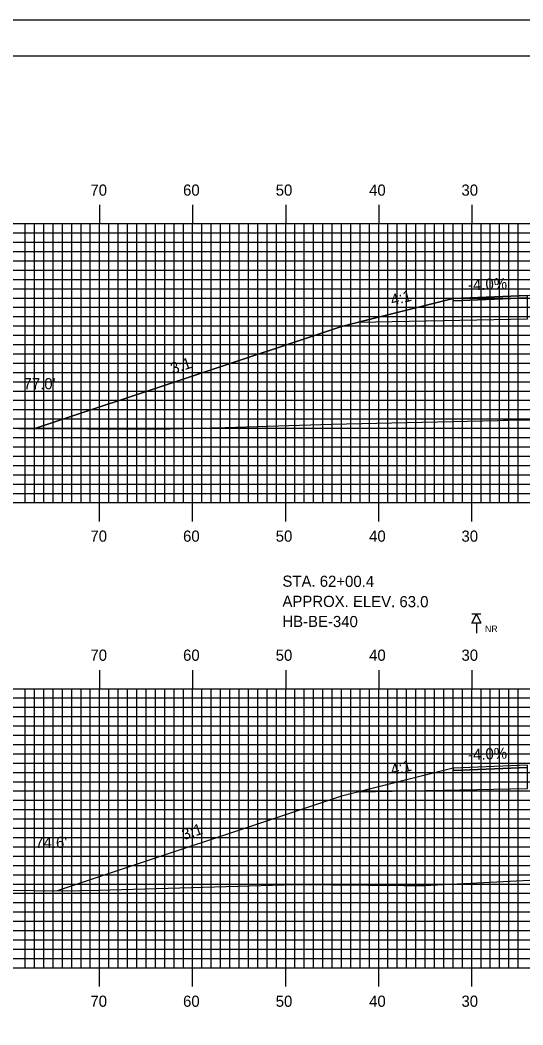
# Model space of a CAD drawing. Extents: x 1757856 to 1758199, y 442591 to 442811.
# Drawn here: x 1757943.1 to 1757997.1, y 442702.5 to 442810.5 of the extents above; entities that cross this region are included whole.
import ezdxf

# ---------------------------------------------------------------- set-up
doc = ezdxf.new("R2010")
doc.units = 0
for name, color, linetype in [('ANNOTATION', 7, 'Continuous'), ('BORDER', 7, 'Continuous'), ('BORING - NO REFUSAL', 7, 'Continuous'), ('D_Roadway_Centerline', 7, 'Continuous'), ('D_Roadway_Edge_Shoulder', 7, 'Continuous'), ('D_Roadway_SlopeLines', 7, 'Continuous'), ('D_Roadway_SubGrade', 7, 'Continuous'), ('D_Text_Standard', 7, 'Continuous'), ('H_V ANNOTATION', 7, 'Continuous'), ('MAJOR', 7, 'Continuous'), ('MINOR', 7, 'Continuous'), ('PLOT BOUNDARY', 7, 'Continuous'), ('S_Roadway_Centerline', 7, 'Continuous')]:
    doc.layers.add(name, color=color, linetype=linetype)

msp = doc.modelspace()

# ---------------------------------------------------------------- linework, layer by layer
at = {"layer": 'BORDER'}
msp.add_lwpolyline([(1757872.02, 442596.67), (1758192.02, 442596.67), (1758192.02, 442806.67), (1757872.02, 442806.67)], close=True, dxfattribs=at)
at = {"layer": 'BORING - NO REFUSAL'}
for p, q in [((1757992.6, 442746.67), (1757991.64, 442746.67)), ((1757992.12, 442745.71), (1757992.12, 442744.65))]:
    msp.add_line(p, q, dxfattribs=at)
msp.add_lwpolyline([(1757992.12, 442746.67), (1757992.6, 442745.71), (1757991.64, 442745.71)], close=True, dxfattribs=at)
at = {"layer": 'D_Roadway_Centerline'}
msp.add_lwpolyline([(1757944.65, 442766.63), (1757977.62, 442777.62), (1757979.45, 442778.07), (1757989.62, 442780.62), (1757997.62, 442780.94), (1758009.62, 442781.18), (1758021.62, 442781.42), (1758033.62, 442781.18), (1758041.62, 442780.86), (1758051.81, 442778.31), (1758060.48, 442780.48)], dxfattribs=at)
at = {"layer": 'D_Roadway_Edge_Shoulder'}
for points in [[(1757997.62, 442780.94), (1757989.62, 442780.62), (1757989.62, 442780.37), (1757997.62, 442780.69)], [(1757997.62, 442730.44), (1757989.62, 442730.12), (1757989.62, 442729.87), (1757997.62, 442730.19)]]:
    msp.add_lwpolyline(points, close=True, dxfattribs=at)
at = {"layer": 'D_Roadway_SlopeLines'}
for points in [[(1757989.62, 442780.62), (1757977.62, 442777.62), (1757944.65, 442766.63)], [(1757989.62, 442730.12), (1757977.62, 442727.12), (1757947.05, 442716.93)]]:
    msp.add_lwpolyline(points, dxfattribs=at)
at = {"layer": 'D_Roadway_SubGrade'}
for points in [[(1757997.62, 442780.27), (1757997.62, 442780.69), (1757989.62, 442780.37), (1757989.62, 442780.62), (1757979.45, 442778.07), (1757997.62, 442778.44)], [(1757997.62, 442729.77), (1757997.62, 442730.19), (1757989.62, 442729.87), (1757989.62, 442730.12), (1757979.45, 442727.57), (1757997.62, 442727.94)]]:
    msp.add_lwpolyline(points, close=True, dxfattribs=at)
at = {"layer": 'MAJOR'}
for p, q in [((1757951.62, 442790.67), (1757951.62, 442788.67)), ((1757961.62, 442790.67), (1757961.62, 442788.67)), ((1757971.62, 442790.67), (1757971.62, 442788.67)), ((1757981.62, 442790.67), (1757981.62, 442788.67)), ((1757991.62, 442790.67), (1757991.62, 442788.67)), ((1757881.62, 442788.67), (1758161.62, 442788.67)), ((1757881.62, 442788.67), (1758161.62, 442788.67)), ((1757951.62, 442758.67), (1757951.62, 442788.67)), ((1757961.62, 442758.67), (1757961.62, 442788.67)), ((1757971.62, 442758.67), (1757971.62, 442788.67)), ((1757981.62, 442758.67), (1757981.62, 442788.67)), ((1757991.62, 442758.67), (1757991.62, 442788.67)), ((1757881.62, 442783.67), (1758161.62, 442783.67)), ((1757881.62, 442778.67), (1758161.62, 442778.67)), ((1757881.62, 442773.67), (1758161.62, 442773.67)), ((1757881.62, 442768.67), (1758161.62, 442768.67)), ((1757881.62, 442763.67), (1758161.62, 442763.67)), ((1757881.62, 442758.67), (1758161.62, 442758.67)), ((1757881.62, 442758.67), (1758161.62, 442758.67)), ((1757951.62, 442756.66), (1757951.62, 442758.67)), ((1757961.62, 442756.66), (1757961.62, 442758.67)), ((1757971.62, 442756.66), (1757971.62, 442758.67)), ((1757981.62, 442756.66), (1757981.62, 442758.67)), ((1757991.62, 442756.66), (1757991.62, 442758.67)), ((1757951.62, 442740.67), (1757951.62, 442738.67)), ((1757961.62, 442740.67), (1757961.62, 442738.67)), ((1757971.62, 442740.67), (1757971.62, 442738.67)), ((1757981.62, 442740.67), (1757981.62, 442738.67)), ((1757991.62, 442740.67), (1757991.62, 442738.67)), ((1757881.62, 442738.67), (1758161.62, 442738.67)), ((1757881.62, 442738.67), (1758161.62, 442738.67)), ((1757951.62, 442708.67), (1757951.62, 442738.67)), ((1757961.62, 442708.67), (1757961.62, 442738.67)), ((1757971.62, 442708.67), (1757971.62, 442738.67)), ((1757981.62, 442708.67), (1757981.62, 442738.67)), ((1757991.62, 442708.67), (1757991.62, 442738.67)), ((1757881.62, 442733.67), (1758161.62, 442733.67)), ((1757881.62, 442728.67), (1758161.62, 442728.67)), ((1757881.62, 442723.67), (1758161.62, 442723.67)), ((1757881.62, 442718.67), (1758161.62, 442718.67)), ((1757881.62, 442713.67), (1758161.62, 442713.67)), ((1757881.62, 442708.67), (1758161.62, 442708.67)), ((1757881.62, 442708.67), (1758161.62, 442708.67)), ((1757951.62, 442706.66), (1757951.62, 442708.67)), ((1757961.62, 442706.66), (1757961.62, 442708.67)), ((1757971.62, 442706.66), (1757971.62, 442708.67)), ((1757981.62, 442706.66), (1757981.62, 442708.67)), ((1757991.62, 442706.66), (1757991.62, 442708.67))]:
    msp.add_line(p, q, dxfattribs=at)
at = {"layer": 'MINOR'}
for p, q in [((1757943.62, 442758.67), (1757943.62, 442788.67)), ((1757944.62, 442758.67), (1757944.62, 442788.67)), ((1757945.62, 442758.67), (1757945.62, 442788.67)), ((1757946.62, 442758.67), (1757946.62, 442788.67)), ((1757947.62, 442758.67), (1757947.62, 442788.67)), ((1757948.62, 442758.67), (1757948.62, 442788.67)), ((1757949.62, 442758.67), (1757949.62, 442788.67)), ((1757950.62, 442758.67), (1757950.62, 442788.67)), ((1757952.62, 442758.67), (1757952.62, 442788.67)), ((1757953.62, 442758.67), (1757953.62, 442788.67)), ((1757954.62, 442758.67), (1757954.62, 442788.67)), ((1757955.62, 442758.67), (1757955.62, 442788.67)), ((1757956.62, 442758.67), (1757956.62, 442788.67)), ((1757957.62, 442758.67), (1757957.62, 442788.67)), ((1757958.62, 442758.67), (1757958.62, 442788.67)), ((1757959.62, 442758.67), (1757959.62, 442788.67)), ((1757960.62, 442758.67), (1757960.62, 442788.67)), ((1757962.62, 442758.67), (1757962.62, 442788.67)), ((1757963.62, 442758.67), (1757963.62, 442788.67)), ((1757964.62, 442758.67), (1757964.62, 442788.67)), ((1757965.62, 442758.67), (1757965.62, 442788.67)), ((1757966.62, 442758.67), (1757966.62, 442788.67)), ((1757967.62, 442758.67), (1757967.62, 442788.67)), ((1757968.62, 442758.67), (1757968.62, 442788.67)), ((1757969.62, 442758.67), (1757969.62, 442788.67)), ((1757970.62, 442758.67), (1757970.62, 442788.67)), ((1757972.62, 442758.67), (1757972.62, 442788.67)), ((1757973.62, 442758.67), (1757973.62, 442788.67)), ((1757974.62, 442758.67), (1757974.62, 442788.67)), ((1757975.62, 442758.67), (1757975.62, 442788.67)), ((1757976.62, 442758.67), (1757976.62, 442788.67)), ((1757977.62, 442758.67), (1757977.62, 442788.67)), ((1757978.62, 442758.67), (1757978.62, 442788.67)), ((1757979.62, 442758.67), (1757979.62, 442788.67)), ((1757980.62, 442758.67), (1757980.62, 442788.67)), ((1757982.62, 442758.67), (1757982.62, 442788.67)), ((1757983.62, 442758.67), (1757983.62, 442788.67)), ((1757984.62, 442758.67), (1757984.62, 442788.67)), ((1757985.62, 442758.67), (1757985.62, 442788.67)), ((1757986.62, 442758.67), (1757986.62, 442788.67)), ((1757987.62, 442758.67), (1757987.62, 442788.67)), ((1757988.62, 442758.67), (1757988.62, 442788.67)), ((1757989.62, 442758.67), (1757989.62, 442788.67)), ((1757990.62, 442758.67), (1757990.62, 442788.67)), ((1757992.62, 442758.67), (1757992.62, 442788.67)), ((1757993.62, 442758.67), (1757993.62, 442788.67)), ((1757994.62, 442758.67), (1757994.62, 442788.67)), ((1757995.62, 442758.67), (1757995.62, 442788.67)), ((1757996.62, 442758.67), (1757996.62, 442788.67)), ((1757881.62, 442787.67), (1758161.62, 442787.67)), ((1757881.62, 442786.67), (1758161.62, 442786.67)), ((1757881.62, 442785.67), (1758161.62, 442785.67)), ((1757881.62, 442784.67), (1758161.62, 442784.67)), ((1757881.62, 442782.67), (1758161.62, 442782.67)), ((1757881.62, 442781.67), (1758161.62, 442781.67)), ((1757881.62, 442780.67), (1758161.62, 442780.67)), ((1757881.62, 442779.67), (1758161.62, 442779.67)), ((1757881.62, 442777.67), (1758161.62, 442777.67)), ((1757881.62, 442776.67), (1758161.62, 442776.67)), ((1757881.62, 442775.67), (1758161.62, 442775.67)), ((1757881.62, 442774.67), (1758161.62, 442774.67)), ((1757881.62, 442772.67), (1758161.62, 442772.67)), ((1757881.62, 442771.67), (1758161.62, 442771.67)), ((1757881.62, 442770.67), (1758161.62, 442770.67)), ((1757881.62, 442769.67), (1758161.62, 442769.67)), ((1757881.62, 442767.67), (1758161.62, 442767.67)), ((1757881.62, 442766.67), (1758161.62, 442766.67)), ((1757881.62, 442765.67), (1758161.62, 442765.67)), ((1757881.62, 442764.67), (1758161.62, 442764.67)), ((1757881.62, 442762.67), (1758161.62, 442762.67)), ((1757881.62, 442761.67), (1758161.62, 442761.67)), ((1757881.62, 442760.67), (1758161.62, 442760.67)), ((1757881.62, 442759.67), (1758161.62, 442759.67)), ((1757943.62, 442708.67), (1757943.62, 442738.67)), ((1757944.62, 442708.67), (1757944.62, 442738.67)), ((1757945.62, 442708.67), (1757945.62, 442738.67)), ((1757946.62, 442708.67), (1757946.62, 442738.67)), ((1757947.62, 442708.67), (1757947.62, 442738.67)), ((1757948.62, 442708.67), (1757948.62, 442738.67)), ((1757949.62, 442708.67), (1757949.62, 442738.67)), ((1757950.62, 442708.67), (1757950.62, 442738.67)), ((1757952.62, 442708.67), (1757952.62, 442738.67)), ((1757953.62, 442708.67), (1757953.62, 442738.67)), ((1757954.62, 442708.67), (1757954.62, 442738.67)), ((1757955.62, 442708.67), (1757955.62, 442738.67)), ((1757956.62, 442708.67), (1757956.62, 442738.67)), ((1757957.62, 442708.67), (1757957.62, 442738.67)), ((1757958.62, 442708.67), (1757958.62, 442738.67)), ((1757959.62, 442708.67), (1757959.62, 442738.67)), ((1757960.62, 442708.67), (1757960.62, 442738.67)), ((1757962.62, 442708.67), (1757962.62, 442738.67)), ((1757963.62, 442708.67), (1757963.62, 442738.67)), ((1757964.62, 442708.67), (1757964.62, 442738.67)), ((1757965.62, 442708.67), (1757965.62, 442738.67)), ((1757966.62, 442708.67), (1757966.62, 442738.67)), ((1757967.62, 442708.67), (1757967.62, 442738.67)), ((1757968.62, 442708.67), (1757968.62, 442738.67)), ((1757969.62, 442708.67), (1757969.62, 442738.67)), ((1757970.62, 442708.67), (1757970.62, 442738.67)), ((1757972.62, 442708.67), (1757972.62, 442738.67)), ((1757973.62, 442708.67), (1757973.62, 442738.67)), ((1757974.62, 442708.67), (1757974.62, 442738.67)), ((1757975.62, 442708.67), (1757975.62, 442738.67)), ((1757976.62, 442708.67), (1757976.62, 442738.67)), ((1757977.62, 442708.67), (1757977.62, 442738.67)), ((1757978.62, 442708.67), (1757978.62, 442738.67)), ((1757979.62, 442708.67), (1757979.62, 442738.67)), ((1757980.62, 442708.67), (1757980.62, 442738.67)), ((1757982.62, 442708.67), (1757982.62, 442738.67)), ((1757983.62, 442708.67), (1757983.62, 442738.67)), ((1757984.62, 442708.67), (1757984.62, 442738.67)), ((1757985.62, 442708.67), (1757985.62, 442738.67)), ((1757986.62, 442708.67), (1757986.62, 442738.67)), ((1757987.62, 442708.67), (1757987.62, 442738.67)), ((1757988.62, 442708.67), (1757988.62, 442738.67)), ((1757989.62, 442708.67), (1757989.62, 442738.67)), ((1757990.62, 442708.67), (1757990.62, 442738.67)), ((1757992.62, 442708.67), (1757992.62, 442738.67)), ((1757993.62, 442708.67), (1757993.62, 442738.67)), ((1757994.62, 442708.67), (1757994.62, 442738.67)), ((1757995.62, 442708.67), (1757995.62, 442738.67)), ((1757996.62, 442708.67), (1757996.62, 442738.67)), ((1757881.62, 442737.67), (1758161.62, 442737.67)), ((1757881.62, 442736.67), (1758161.62, 442736.67)), ((1757881.62, 442735.67), (1758161.62, 442735.67)), ((1757881.62, 442734.67), (1758161.62, 442734.67)), ((1757881.62, 442732.67), (1758161.62, 442732.67)), ((1757881.62, 442731.67), (1758161.62, 442731.67)), ((1757881.62, 442730.67), (1758161.62, 442730.67)), ((1757881.62, 442729.67), (1758161.62, 442729.67)), ((1757881.62, 442727.67), (1758161.62, 442727.67)), ((1757881.62, 442726.67), (1758161.62, 442726.67)), ((1757881.62, 442725.67), (1758161.62, 442725.67)), ((1757881.62, 442724.67), (1758161.62, 442724.67)), ((1757881.62, 442722.67), (1758161.62, 442722.67)), ((1757881.62, 442721.67), (1758161.62, 442721.67)), ((1757881.62, 442720.67), (1758161.62, 442720.67)), ((1757881.62, 442719.67), (1758161.62, 442719.67)), ((1757881.62, 442717.67), (1758161.62, 442717.67)), ((1757881.62, 442716.67), (1758161.62, 442716.67)), ((1757881.62, 442715.67), (1758161.62, 442715.67)), ((1757881.62, 442714.67), (1758161.62, 442714.67)), ((1757881.62, 442712.67), (1758161.62, 442712.67)), ((1757881.62, 442711.67), (1758161.62, 442711.67)), ((1757881.62, 442710.67), (1758161.62, 442710.67)), ((1757881.62, 442709.67), (1758161.62, 442709.67))]:
    msp.add_line(p, q, dxfattribs=at)
at = {"layer": 'PLOT BOUNDARY'}
msp.add_lwpolyline([(1757855.84, 442590.55), (1758195.84, 442590.55), (1758195.84, 442810.55), (1757855.84, 442810.55)], close=True, dxfattribs=at)
at = {"layer": 'S_Roadway_Centerline'}
for points in [[(1757942.94, 442766.64), (1757957.7, 442766.56), (1757965.12, 442766.76), (1757976.56, 442767.11), (1757994.44, 442767.5), (1757995.02, 442767.52), (1757995.51, 442767.52), (1758007.66, 442767.6), (1758013.74, 442767.97), (1758029.7, 442767.75), (1758033.59, 442767.78), (1758041.83, 442767.95), (1758055.74, 442768.41), (1758059.36, 442768.58), (1758072.67, 442768.91), (1758091.05, 442768.72)], [(1757938.97, 442717.05), (1757947.5, 442716.92), (1757951.51, 442717), (1757965.23, 442717.4), (1757972.73, 442717.6), (1757984.33, 442717.52), (1757986.5, 442717.52), (1757999.99, 442718.19), (1758004.22, 442718.16), (1758017.53, 442717.91), (1758020.15, 442717.83), (1758021.64, 442717.88), (1758029.2, 442717.87), (1758041.85, 442718.04), (1758047.73, 442718.09), (1758056.34, 442718.22), (1758061.68, 442718.34), (1758077.96, 442718.66), (1758080.02, 442718.69), (1758080.79, 442718.7), (1758100.24, 442718.9)]]:
    msp.add_lwpolyline(points, dxfattribs=at)

# ---------------------------------------------------------------- texts
at = {"layer": 'ANNOTATION'}
for s, rotation, p in [('-4.0%', 2.2906, (1757991.25, 442781.48)), ('4:1', 14.0362, (1757983.07, 442779.84)), ('3:1', 18.4348, (1757959.48, 442772.48)), ('-4.0%', 2.2906, (1757991.25, 442730.98)), ('4:1', 14.0362, (1757983.07, 442729.34)), ('3:1', 18.4348, (1757960.68, 442722.38))]:
    msp.add_text(s, height=1.2, rotation=rotation, dxfattribs=at).set_placement(p)
at = {"layer": 'BORING - NO REFUSAL'}
for s, p in [('STA. 62+00.4', (1757971.27, 442749.63)), ('APPROX. ELEV. 63.0', (1757971.27, 442747.47)), ('HB-BE-340', (1757971.26, 442745.31))]:
    msp.add_text(s, height=1.2, rotation=359.8142, dxfattribs=at).set_placement(p)
msp.add_text('NR', height=0.7, dxfattribs=at).set_placement((1757993.05, 442744.75))
at = {"layer": 'D_Text_Standard'}
for s, p in [("77.0'", (1757943.44, 442770.86)), ("74.6'", (1757944.7, 442721.54))]:
    msp.add_text(s, height=1.2, dxfattribs=at).set_placement(p)
at = {"layer": 'H_V ANNOTATION'}
for s, p in [('70', (1757950.63, 442791.67)), ('60', (1757960.59, 442791.67)), ('50', (1757970.55, 442791.67)), ('40', (1757980.59, 442791.67)), ('30', (1757990.52, 442791.67)), ('70', (1757950.63, 442754.47)), ('60', (1757960.59, 442754.47)), ('50', (1757970.55, 442754.47)), ('40', (1757980.59, 442754.47)), ('30', (1757990.52, 442754.47)), ('70', (1757950.63, 442741.67)), ('60', (1757960.59, 442741.67)), ('50', (1757970.55, 442741.67)), ('40', (1757980.59, 442741.67)), ('30', (1757990.52, 442741.67)), ('70', (1757950.63, 442704.47)), ('60', (1757960.59, 442704.47)), ('50', (1757970.55, 442704.47)), ('40', (1757980.59, 442704.47)), ('30', (1757990.52, 442704.47))]:
    msp.add_text(s, height=1.2, dxfattribs=at).set_placement(p)

doc.saveas('drawing.dxf')
